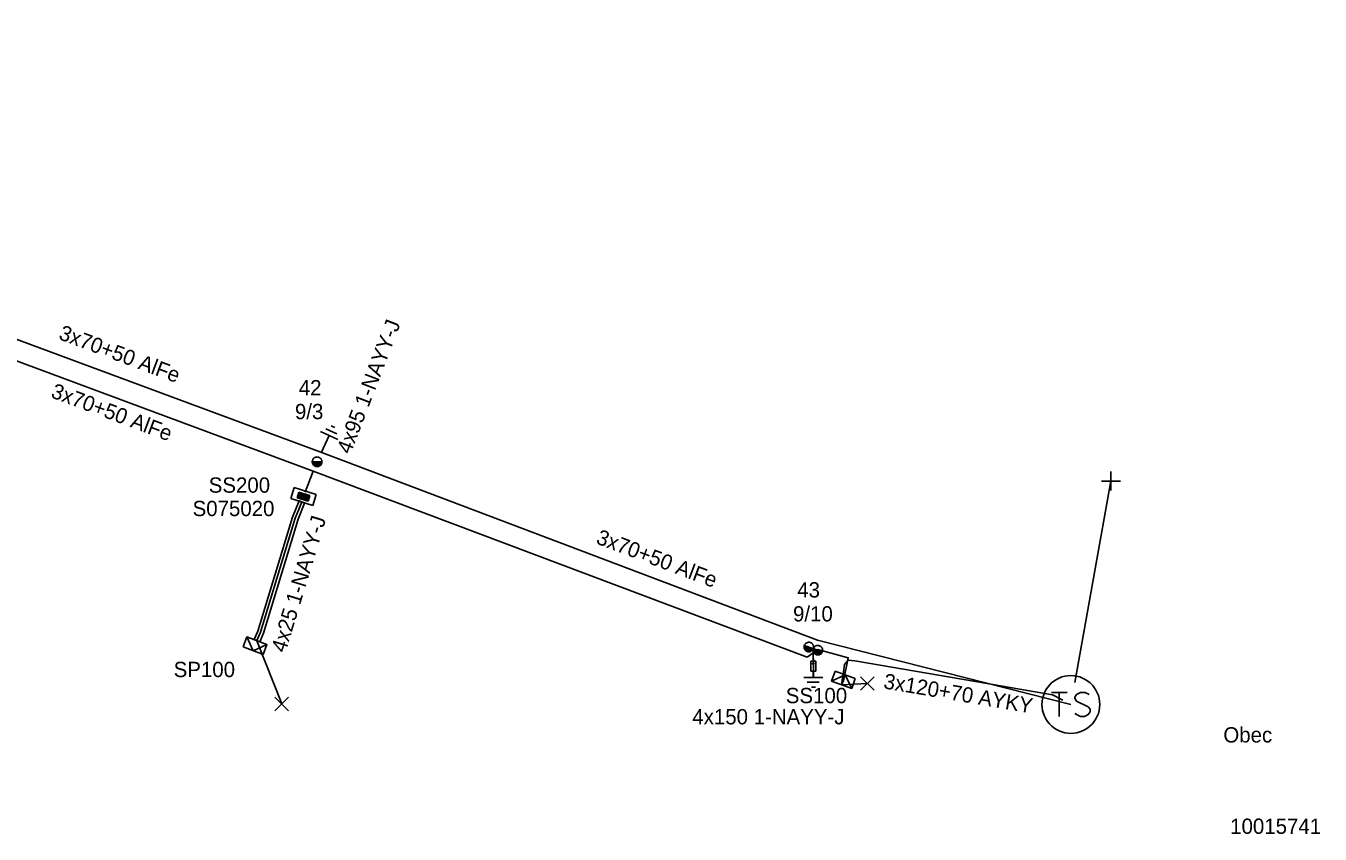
# Model space of a CAD drawing. Extents: x -788458 to -786145, y -1154772 to -1152372.
# Drawn here: x -787287.4 to -787202.7, y -1152780.4 to -1152727.5 of the extents above; entities that cross this region are included whole.
import ezdxf

# ---------------------------------------------------------------- set-up
doc = ezdxf.new("R2010")
doc.units = 0
for name, color, linetype in [('Vrstva 1', 7, 'Continuous'), ('Vrstva 12', 7, 'Continuous'), ('Vrstva 13', 7, 'Continuous'), ('Vrstva 14', 7, 'Continuous'), ('Vrstva 15', 7, 'Continuous'), ('Vrstva 16', 7, 'Continuous'), ('Vrstva 2', 7, 'Continuous'), ('Vrstva 20', 7, 'Continuous'), ('Vrstva 25', 7, 'Continuous'), ('Vrstva 26', 7, 'Continuous'), ('Vrstva 27', 7, 'Continuous'), ('Vrstva 28', 7, 'Continuous'), ('Vrstva 29', 7, 'Continuous'), ('Vrstva 30', 7, 'Continuous'), ('Vrstva 31', 7, 'Continuous'), ('Vrstva 33', 7, 'Continuous'), ('Vrstva 34', 7, 'Continuous'), ('Vrstva 5', 7, 'Continuous'), ('Vrstva 52', 7, 'Continuous'), ('Vrstva 54', 7, 'Continuous'), ('Vrstva 59', 7, 'Continuous'), ('Vrstva 6', 7, 'Continuous'), ('Vrstva 8', 7, 'Continuous'), ('Vrstva 9', 7, 'Continuous')]:
    doc.layers.add(name, color=color, linetype=linetype)

# ---------------------------------------------------------------- blocks, each defined once
blk = doc.blocks.new('NN440')
at = {"layer": 'Vrstva 2'}
for points in [[(0.63, 0), (0.63, 0.06), (0.62, 0.13), (0.6, 0.19), (0.58, 0.25), (0.55, 0.31), (0.51, 0.37), (0.47, 0.42), (0.42, 0.46), (0.37, 0.51), (0.32, 0.54), (0.26, 0.57), (0.2, 0.59), (0.13, 0.61), (0.07, 0.62), (0, 0.63), (-0.06, 0.62), (-0.13, 0.61), (-0.19, 0.59), (-0.26, 0.57), (-0.31, 0.54), (-0.37, 0.51), (-0.42, 0.46), (-0.47, 0.42), (-0.51, 0.37), (-0.54, 0.31), (-0.57, 0.25), (-0.6, 0.19), (-0.62, 0.13), (-0.63, 0.06), (-0.63, 0), (-0.63, -0.07), (-0.62, -0.14), (-0.6, -0.2), (-0.57, -0.26), (-0.54, -0.32), (-0.51, -0.37), (-0.47, -0.43), (-0.42, -0.47), (-0.37, -0.51), (-0.31, -0.55), (-0.26, -0.58), (-0.19, -0.6), (-0.13, -0.62), (-0.06, -0.63), (0, -0.63), (0.07, -0.63), (0.13, -0.62), (0.2, -0.6), (0.26, -0.58), (0.32, -0.55), (0.37, -0.51), (0.42, -0.47), (0.47, -0.43), (0.51, -0.37), (0.55, -0.32), (0.58, -0.26), (0.6, -0.2), (0.62, -0.14), (0.63, -0.07), (0.63, 0)], [(-0.63, 0), (0.63, 0)], [(-0.6, -0.18), (0.57, -0.18)], [(-0.51, -0.32), (0.5, -0.32)], [(-0.37, -0.47), (0.35, -0.47)]]:
    blk.add_lwpolyline(points, dxfattribs=at)
blk = doc.blocks.new('NN450')
at = {"layer": 'Vrstva 2'}
for points in [[(0, 0), (0, 0.07), (-0.01, 0.13), (-0.03, 0.19), (-0.05, 0.25), (-0.08, 0.31), (-0.12, 0.37), (-0.16, 0.42), (-0.21, 0.46), (-0.26, 0.51), (-0.31, 0.54), (-0.37, 0.57), (-0.43, 0.59), (-0.5, 0.61), (-0.56, 0.62), (-0.63, 0.62), (-0.69, 0.62), (-0.75, 0.61), (-0.82, 0.59), (-0.88, 0.57), (-0.94, 0.54), (-0.99, 0.51), (-1.04, 0.46), (-1.09, 0.42), (-1.13, 0.37), (-1.17, 0.31), (-1.2, 0.25), (-1.22, 0.19), (-1.24, 0.13), (-1.25, 0.07), (-1.25, 0), (-1.25, -0.07), (-1.24, -0.13), (-1.22, -0.19), (-1.2, -0.25), (-1.17, -0.31), (-1.13, -0.37), (-1.09, -0.42), (-1.04, -0.46), (-0.99, -0.51), (-0.94, -0.54), (-0.88, -0.57), (-0.82, -0.59), (-0.75, -0.61), (-0.69, -0.62), (-0.62, -0.63), (-0.56, -0.62), (-0.5, -0.61), (-0.43, -0.59), (-0.37, -0.57), (-0.31, -0.54), (-0.26, -0.51), (-0.21, -0.46), (-0.16, -0.42), (-0.12, -0.37), (-0.08, -0.31), (-0.05, -0.25), (-0.03, -0.19), (-0.01, -0.13), (0, -0.07), (0, 0)], [(1.25, 0), (1.25, 0.07), (1.24, 0.13), (1.22, 0.19), (1.2, 0.25), (1.17, 0.31), (1.13, 0.37), (1.09, 0.42), (1.04, 0.46), (0.99, 0.51), (0.94, 0.54), (0.88, 0.57), (0.82, 0.59), (0.75, 0.61), (0.69, 0.62), (0.62, 0.62), (0.56, 0.62), (0.5, 0.61), (0.43, 0.59), (0.37, 0.57), (0.31, 0.54), (0.26, 0.51), (0.21, 0.46), (0.16, 0.42), (0.12, 0.37), (0.08, 0.31), (0.05, 0.25), (0.03, 0.19), (0.01, 0.13), (0, 0.07), (0, 0), (0, -0.07), (0.01, -0.13), (0.03, -0.19), (0.05, -0.25), (0.08, -0.31), (0.12, -0.37), (0.16, -0.42), (0.21, -0.46), (0.26, -0.51), (0.31, -0.54), (0.37, -0.57), (0.43, -0.59), (0.5, -0.61), (0.56, -0.62), (0.63, -0.63), (0.69, -0.62), (0.75, -0.61), (0.82, -0.59), (0.88, -0.57), (0.94, -0.54), (0.99, -0.51), (1.04, -0.46), (1.09, -0.42), (1.13, -0.37), (1.17, -0.31), (1.2, -0.25), (1.22, -0.19), (1.24, -0.13), (1.25, -0.07), (1.25, 0)], [(-1.25, 0), (1.25, 0)], [(-1.23, -0.16), (-0.02, -0.16)], [(-1.16, -0.32), (-0.09, -0.32)], [(-1.03, -0.47), (-0.22, -0.47)], [(0.02, -0.16), (1.23, -0.16)], [(0.09, -0.32), (1.16, -0.32)], [(0.22, -0.47), (1.03, -0.47)]]:
    blk.add_lwpolyline(points, dxfattribs=at)
blk = doc.blocks.new('NN800')
at = {"layer": 'Vrstva 1'}
for points in [[(-0.442, 0.442), (0.442, -0.442)], [(-0.442, -0.442), (0.442, 0.442)]]:
    blk.add_lwpolyline(points, dxfattribs=at)
blk = doc.blocks.new('NN820')
at = {"layer": 'Vrstva 13'}
for points in [[(-0.003, 0.004), (-0.003, -1.049)], [(-0.165, -0.813), (0.165, -0.813)], [(-0.165, -1.473), (-0.165, -0.813)], [(0.165, -0.813), (0.165, -1.473)], [(0.165, -1.473), (-0.165, -1.473)], [(-0.003, -1.049), (-0.062, -0.926)], [(-0.003, -1.049), (0.057, -0.926)], [(-0.003, -1.473), (-0.003, -1.871)]]:
    blk.add_lwpolyline(points, dxfattribs=at)
blk = doc.blocks.new('NN620')
at = {"layer": 'Vrstva 8'}
for points in [[(0.752, 0.004), (-0.748, 0.004)], [(-0.748, 0.004), (-0.748, -0.746)], [(0.752, -0.746), (0.752, 0.004)], [(-0.748, -0.746), (0.752, -0.746)], [(0.368, -0.18), (-0.376, -0.18)], [(-0.376, -0.18), (-0.376, -0.558)], [(-0.376, -0.558), (0.368, -0.558)], [(0.321, -0.227), (-0.329, -0.227)], [(-0.329, -0.227), (-0.329, -0.51)], [(-0.329, -0.51), (0.321, -0.51)], [(0.274, -0.274), (-0.281, -0.274)], [(-0.281, -0.274), (-0.281, -0.463)], [(-0.281, -0.463), (0.274, -0.463)], [(0.227, -0.321), (-0.234, -0.321)], [(-0.234, -0.321), (-0.234, -0.416)], [(-0.234, -0.416), (0.227, -0.416)], [(-0.193, -0.369), (0.185, -0.369)], [(0.227, -0.416), (0.227, -0.321)], [(0.274, -0.463), (0.274, -0.274)], [(0.321, -0.51), (0.321, -0.227)], [(0.368, -0.558), (0.368, -0.18)]]:
    blk.add_lwpolyline(points, dxfattribs=at)
blk = doc.blocks.new('NN630')
at = {"layer": 'Vrstva 9'}
for points in [[(-0.003, -0.7), (-0.703, 0)], [(-0.703, -0.7), (-0.703, 0), (0.697, 0), (0.697, -0.7)], [(-0.703, -0.7), (0.697, -0.7)], [(-0.003, -0.7), (0.697, 0)]]:
    blk.add_lwpolyline(points, dxfattribs=at)
blk = doc.blocks.new('NN810')
at = {"layer": 'Vrstva 14'}
for points in [[(0.004, -0.64), (0.004, -1.89)], [(0.629, -1.89), (-0.621, -1.89)], [(0.388, -2.2), (-0.399, -2.2)], [(0.004, -2.515), (-0.124, -2.515)], [(0.137, -2.515), (0.004, -2.515)]]:
    blk.add_lwpolyline(points, dxfattribs=at)
blk = doc.blocks.new('NN610')
at = {"layer": 'Vrstva 6'}
for points in [[(1.883, -0.001), (1.872, 0.196), (1.841, 0.392), (1.79, 0.583), (1.718, 0.768), (1.629, 0.943), (1.521, 1.109), (1.397, 1.263), (1.257, 1.403), (1.103, 1.527), (0.937, 1.635), (0.761, 1.725), (0.577, 1.796), (0.19, 1.878), (0.19, 1.878), (-0.007, 1.889), (-0.205, 1.878), (-0.401, 1.847), (-0.591, 1.796), (-0.777, 1.725), (-0.952, 1.635), (-1.118, 1.527), (-1.272, 1.403), (-1.412, 1.263), (-1.536, 1.109), (-1.644, 0.943), (-1.734, 0.768), (-1.805, 0.583), (-1.856, 0.392), (-1.887, 0.196), (-1.898, -0.001), (-1.887, -0.199), (-1.856, -0.395), (-1.805, -0.585), (-1.734, -0.77), (-1.644, -0.946), (-1.536, -1.112), (-1.411, -1.266), (-1.272, -1.405), (-1.118, -1.53), (-0.952, -1.638), (-0.776, -1.728), (-0.591, -1.799), (-0.401, -1.85), (-0.205, -1.881), (-0.007, -1.892), (0.19, -1.881), (0.385, -1.85), (0.577, -1.799), (0.761, -1.728), (0.937, -1.638), (1.103, -1.53), (1.257, -1.405), (1.397, -1.266), (1.521, -1.112), (1.629, -0.946), (1.718, -0.77), (1.79, -0.585), (1.841, -0.395), (1.872, -0.199), (1.883, -0.001)], [(-1.269, 0.782), (-0.261, 0.782)], [(-0.765, 0.782), (-0.765, -0.792)], [(1.188, 0.656), (0.936, 0.782), (0.621, 0.782), (0.369, 0.656), (0.243, 0.468), (0.243, 0.404), (0.369, 0.216), (1.125, -0.162), (1.251, -0.32), (1.251, -0.478), (1.125, -0.666), (0.873, -0.792), (0.621, -0.792), (0.495, -0.73), (0.243, -0.604)]]:
    blk.add_lwpolyline(points, dxfattribs=at)

msp = doc.modelspace()

# ---------------------------------------------------------------- linework, layer by layer
at = {"layer": 'Vrstva 1'}
for points in [[(-787327.741, -1152703.401), (-787337.42, -1152723.22), (-787317.82, -1152737.159), (-787292.344, -1152746.434), (-787268.103, -1152755.42), (-787235.599, -1152767.697), (-787219.01, -1152771.91)], [(-787268.588, -1152756.647), (-787292.795, -1152747.666), (-787318.461, -1152738.272)], [(-787236.264, -1152768.83), (-787268.588, -1152756.647)]]:
    msp.add_lwpolyline(points, dxfattribs=at)
at = {"layer": 'Vrstva 20'}
msp.add_lwpolyline([(-787272.463, -1152767.66), (-787272.228, -1152767.121), (-787269.959, -1152759.663), (-787269.525, -1152758.595), (-787269.155, -1152758.745), (-787269.581, -1152759.797), (-787271.852, -1152767.259), (-787272.097, -1152767.82)], close=True, dxfattribs=at)
at = {"layer": 'Vrstva 5'}
for points in [[(-787268.588, -1152756.647), (-787269.114, -1152758.018)], [(-787236.264, -1152768.83), (-787235.577, -1152768.324), (-787233.58, -1152768.86), (-787233.907, -1152770.378), (-787234.02, -1152770.63)], [(-787234.02, -1152770.63), (-787233.893, -1152769.772), (-787233.82, -1152769.3), (-787233.6, -1152769.01), (-787233.15, -1152769.06), (-787225.25, -1152770.4), (-787220.21, -1152771.29), (-787219.538, -1152771.637)]]:
    msp.add_lwpolyline(points, dxfattribs=at)
at = {"layer": 'Vrstva 52'}
msp.add_lwpolyline([(-787269.34, -1152758.67), (-787269.561, -1152759.215), (-787269.77, -1152759.73), (-787272.04, -1152767.19), (-787272.28, -1152767.74)], dxfattribs=at)
at = {"layer": 'Vrstva 59'}
for points in [[(-787218.766, -1152770.48), (-787216.4, -1152757.3)], [(-787272.276, -1152767.742), (-787270.658, -1152771.882)], [(-787234.02, -1152770.63), (-787232.342, -1152770.537)]]:
    msp.add_lwpolyline(points, dxfattribs=at)

# ---------------------------------------------------------------- block references
at = {"layer": 'Vrstva 13', "xscale": 0.5, "yscale": 0.5}
msp.add_blockref('NN440', (-787268.34, -1152756.04), dxfattribs=at)
at = {"layer": 'Vrstva 13', "xscale": 0.5, "yscale": 0.5, "rotation": -19.11575091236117}
msp.add_blockref('NN450', (-787235.87, -1152768.26), dxfattribs=at)
at = {"layer": 'Vrstva 15', "rotation": 155.26633963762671}
msp.add_blockref('NN810', (-787268.34, -1152756.04), dxfattribs=at)
at = {"layer": 'Vrstva 15'}
msp.add_blockref('NN810', (-787235.87, -1152768.26), dxfattribs=at)
at = {"layer": 'Vrstva 16'}
msp.add_blockref('NN820', (-787235.87, -1152768.26), dxfattribs=at)
at = {"layer": 'Vrstva 25', "rotation": -0.018891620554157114}
msp.add_blockref('NN610', (-787219.01, -1152771.91), dxfattribs=at)
at = {"layer": 'Vrstva 28', "rotation": 162.72011063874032}
msp.add_blockref('NN620', (-787269.34, -1152758.67), dxfattribs=at)
at = {"layer": 'Vrstva 31'}
for p, rotation in [((-787272.28, -1152767.74), -20.566091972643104), ((-787234.02, -1152770.63), 160.4160061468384)]:
    msp.add_blockref('NN630', p, dxfattribs=dict(at, rotation=rotation))
at = {"layer": 'Vrstva 34', "rotation": 45}
msp.add_blockref('NN800', (-787216.4, -1152757.3), dxfattribs=at)
at = {"layer": 'Vrstva 34'}
for p in [(-787232.342, -1152770.537), (-787270.658, -1152771.882)]:
    msp.add_blockref('NN800', p, dxfattribs=at)

# ---------------------------------------------------------------- texts
at = {"layer": 'Vrstva 12'}
for s, p in [('9/3', (-787269.79, -1152753.256)), ('9/10', (-787237.198, -1152766.485))]:
    msp.add_text(s, height=1, dxfattribs=at).set_placement(p)
at = {"layer": 'Vrstva 14'}
for s, p in [('42', (-787269.54, -1152751.696)), ('43', (-787236.923, -1152764.915))]:
    msp.add_text(s, height=1, dxfattribs=at).set_placement(p)
at = {"layer": 'Vrstva 2'}
for rotation, p in [(339.573, (-787285.309, -1152748.006)), (339.518, (-787285.82, -1152751.812)), (339.308, (-787250.149, -1152761.367))]:
    msp.add_text('3x70+50 AlFe', height=1, rotation=rotation, dxfattribs=at).set_placement(p)
at = {"layer": 'Vrstva 26'}
msp.add_text('10015741', height=1, dxfattribs=at).set_placement((-787208.594, -1152780.376))
at = {"layer": 'Vrstva 27'}
msp.add_text('Obec', height=1, dxfattribs=at).set_placement((-787209.041, -1152774.4))
at = {"layer": 'Vrstva 29'}
msp.add_text('S075020', height=1, dxfattribs=at).set_placement((-787276.487, -1152759.595))
at = {"layer": 'Vrstva 30'}
msp.add_text('SS200', height=1, dxfattribs=at).set_placement((-787275.432, -1152758.064))
at = {"layer": 'Vrstva 33'}
for s, p in [('SP100', (-787277.726, -1152770.123)), ('SS100', (-787237.671, -1152771.829))]:
    msp.add_text(s, height=1, dxfattribs=at).set_placement(p)
at = {"layer": 'Vrstva 54'}
msp.add_text('4x25 1-NAYY-J', height=1, rotation=73.076, dxfattribs=at).set_placement((-787270.414, -1152768.577))
at = {"layer": 'Vrstva 6'}
for s, rotation, p in [('4x95 1-NAYY-J', 69.01, (-787266.159, -1152755.594)), ('3x120+70 AYKY', 350.373, (-787231.322, -1152770.856))]:
    msp.add_text(s, height=1, rotation=rotation, dxfattribs=at).set_placement(p)
msp.add_text('4x150 1-NAYY-J', height=1, dxfattribs=at).set_placement((-787243.79, -1152773.213))

doc.saveas('drawing.dxf')
